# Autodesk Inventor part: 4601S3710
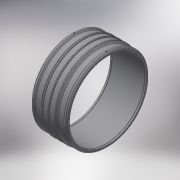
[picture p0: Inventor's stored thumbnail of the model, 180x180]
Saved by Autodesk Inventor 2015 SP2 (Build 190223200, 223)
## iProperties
Created: 2017-06
Part Number: 4601S3710
Material: Generic
Description: PLASSON SUPER LIGHTFIT 710 MM
Document SubType Name: Modeling
Designer: KIM
Mass: 22663.6 g
Surface Area: 19860.2 cm^2
Volume: 22663.6 cm^3
Density: 1 g/cm^3
Appearance: Default
Author: KIM
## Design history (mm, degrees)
derived "4601S3.ipt"
feature "Solid1::4601S3.ipt"
tag "TaggingFeature1"
body "Solid1"
other parameters: "d14" = 17.6296, "d19" = 3.52592, "d20" = 168 deg, "d22" = 776, "d23" = 775, "d24" = 752.72, "d25" = 135 deg, "d26" = 152, "d27" = 135 deg, "d29" = 388, "d35" = 15, "d39" = 0, "d40" = 4, "d41" = 14, "d42" = 0, "d43" = 135 deg, "d44" = 41.8, "d45" = 15.2, "d46" = 15.2, "d47" = 15.2, "d48" = 759.5, "d49" = 775, "d50" = 3.875, "d51" = 6, "d52" = 0, "D_" = 775, "A_" = 388, "d_2" = 12
